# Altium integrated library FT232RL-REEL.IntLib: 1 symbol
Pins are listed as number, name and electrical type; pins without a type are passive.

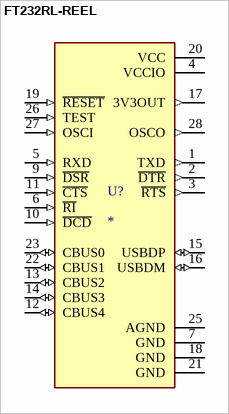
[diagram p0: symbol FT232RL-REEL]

## FT232RL-REEL
designator U?
USB Full Speed to Serial UART IC, Includes Oscillator and EEPROM - SSOP-28; MP: FT232RL-REEL
footprint SOP65P780X200-28N
pins: 1 TXD (out), 2 ~{DTR} (out), 3 ~{RTS} (out), 4 VCCIO (power), 5 RXD (in), 6 ~{RI} (in), 7 GND (power), 9 ~{DSR} (in), 10 ~{DCD} (in), 11 ~{CTS} (in), 12 CBUS4 (io), 13 CBUS2 (io), 14 CBUS3 (io), 15 USBDP (io), 16 USBDM (io), 17 3V3OUT (out), 18 GND (power), 19 ~{RESET} (in), 20 VCC (power), 21 GND (power), 22 CBUS1 (io), 23 CBUS0 (io), 25 AGND (power), 26 TEST (in), 27 OSCI (in), 28 OSCO (out)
